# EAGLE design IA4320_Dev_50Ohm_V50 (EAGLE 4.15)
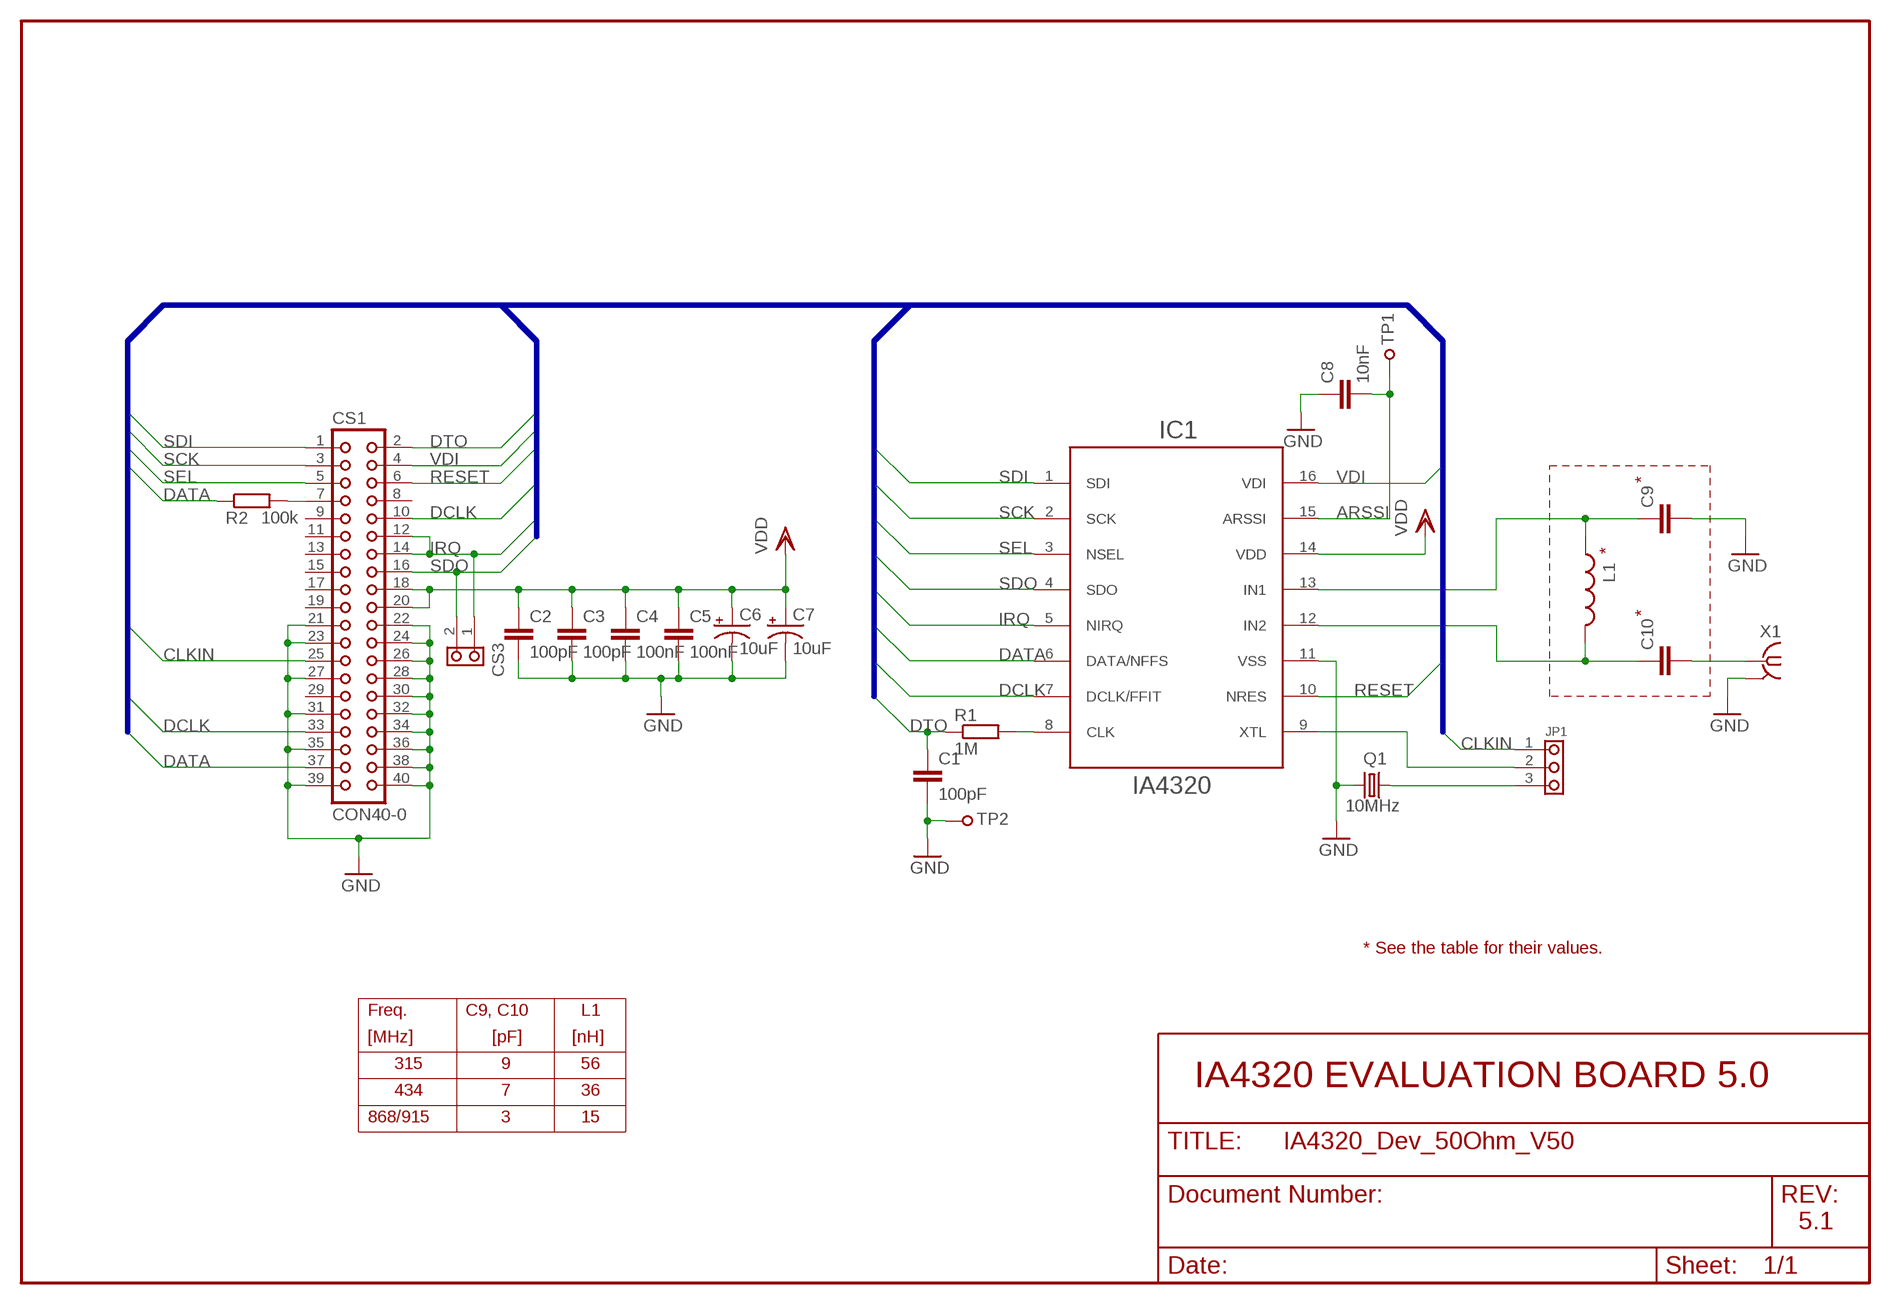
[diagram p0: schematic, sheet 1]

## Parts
C1  100pF  C-EUC0603  [C0603]
C2  100pF  C-EUC0603  [C0603]
C3  100pF  C-EUC0603  [C0603]
C4  100nF  C-EUC0603  [C0603]
C5  100nF  C-EUC0603  [C0603]
C6  10uF  CPOL-USA/3216-18R  [A/3216-18R]
C7  10uF  CPOL-USA/3216-18R  [A/3216-18R]
C8  10nF  C-EUC0603  [C0603]
C9  C-EUC0603  [C0603]
C10  C-EUC0603  [C0603]
CS1  CON40-0  [PANDUIT-057-040-0-INTEGRATION]
CS3  CRS-2  [CRS-2]
IC1  IA4320  RITATSSOP  [TSSOP-16]
JP1  JUMPER3  [PIN3]
L1  INDUCTCOILCRAFT-0805  [L2012]
Q1  10MHz  CRYTALSM49  [SM49]
R1  1M  R-EU_R0603  [R0603]
R2  100k  R-EU_R0603  [R0603]
TP1  TESTPOINT  TESTPOINT39MIL  [TESTPOINT1,0]
TP2  TESTPOINT39MIL  [TESTPOINT1,0]
X1  BU-SMA-H  [BU-SMA-H]

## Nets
ARSSI: C8.2 IC1.15(ARSSI) TP1.1
CLKIN: CS1.25 JP1.1
DATA: CS1.37 IC1.6(DATA/NFFS) R2.1
DCLK: CS1.10 CS1.33 IC1.7(DCLK/FFIT)
DTO: C1.1 CS1.2 R1.1
GND: C1.2 C2.2 C3.2 C4.2 C5.2 C6.- C7.- C8.1 C9.2 CS1.21 CS1.22 CS1.23 CS1.24 CS1.26 CS1.27 CS1.28 CS1.30 CS1.31 CS1.32 CS1.34 CS1.35 CS1.36 CS1.38 CS1.39 CS1.40 IC1.11(VSS) Q1.2 TP2.1 X1.2(GND)
IRQ: CS1.12 CS1.14 CS3.1(A) IC1.5(NIRQ)
N$1: CS1.7 R2.2
N$2: C9.1 IC1.13(IN1) L1.1
N$3: IC1.8(CLK) R1.2
N$4: IC1.9(XTL) JP1.2
N$5: C10.1 IC1.12(IN2) L1.2
N$6: JP1.3 Q1.1
N$8: C10.2 X1.1
RESET: CS1.6 IC1.10(NRES)
SCK: CS1.3 IC1.2(SCK)
SDI: CS1.1 IC1.1(SDI)
SDO: CS1.16 CS3.2(B) IC1.4(SDO)
SEL: CS1.5 IC1.3(NSEL)
VDD: C2.1 C3.1 C4.1 C5.1 C6.+ C7.+ CS1.18 CS1.20 IC1.14(VDD)
VDI: CS1.4 IC1.16(VDI)
Unconnected: CS1.8 CS1.9 CS1.11 CS1.13 CS1.15 CS1.17 CS1.19 CS1.29

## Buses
B$1

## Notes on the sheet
- *
- *
- *
- * See the table for their values.
- Freq. | C9, C10 | L1
- [MHz] | [pF] | [nH]
- 315 | 9 | 56
- IA4320 EVALUATION BOARD 5.0
- 434 | 7 | 36
- 868/915 | 3 | 15
- 5.1

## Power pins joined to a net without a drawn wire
GND: X1.3(GND) X1.4(GND) X1.5(GND)

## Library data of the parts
C1-C5 C8-C10 = rcl:C-EU: CAPACITOR, European symbol
C6 C7 = rcl:CPOL-US: POLARIZED CAPACITOR, American symbol
CS1 = lve:CON40
CS3 = lve:CRS-2: 2.54mm-es tuskesor krimpelheto csatlakozohoz
IC1 = lve:RITA: RITA
JP1 = lve:JUMPER3
L1 = lve:INDUCT
Q1 = crystal:CRYTAL: CRYSTAL
R1 R2 = rcl:R-EU_: RESISTOR, European symbol
TP1 TP2 = lve:TESTPOINT
X1 = con-coax:BU-SMA-H: FEMALE SMA CONNECTOR Radiall distributor RS 193-9325

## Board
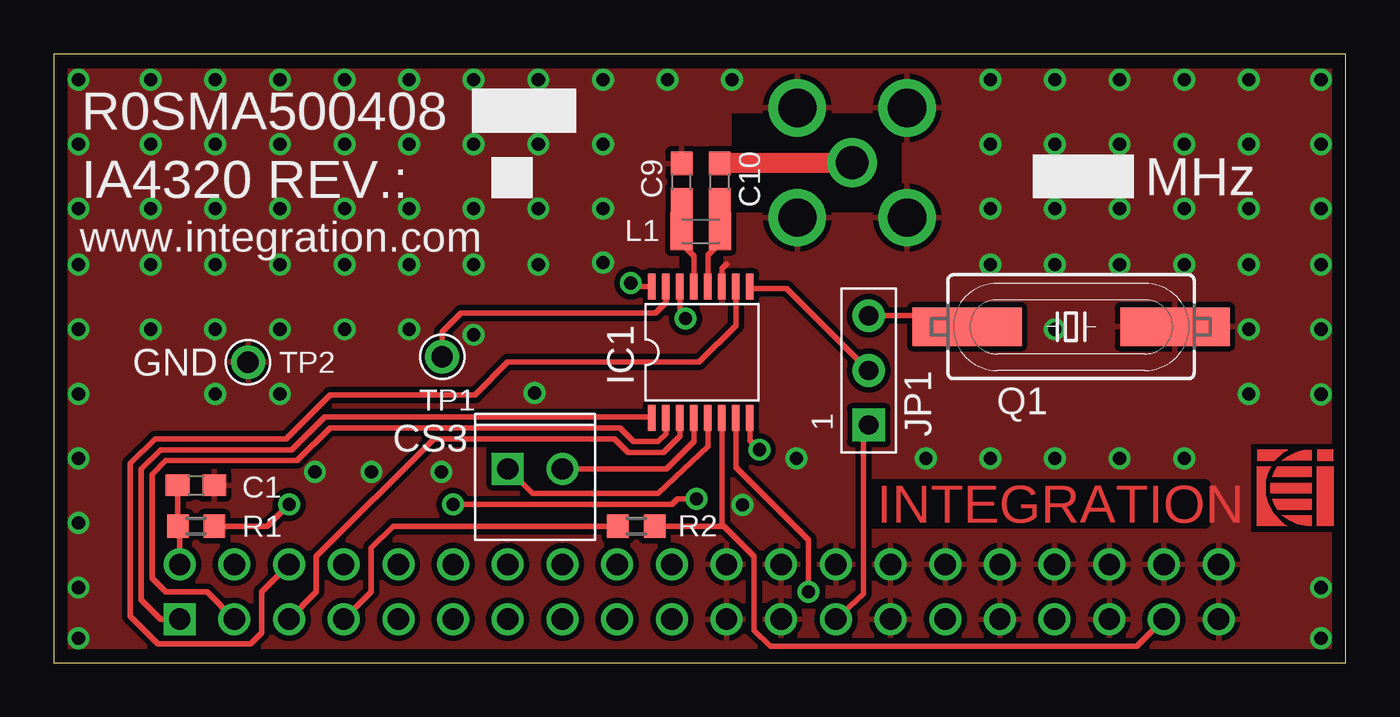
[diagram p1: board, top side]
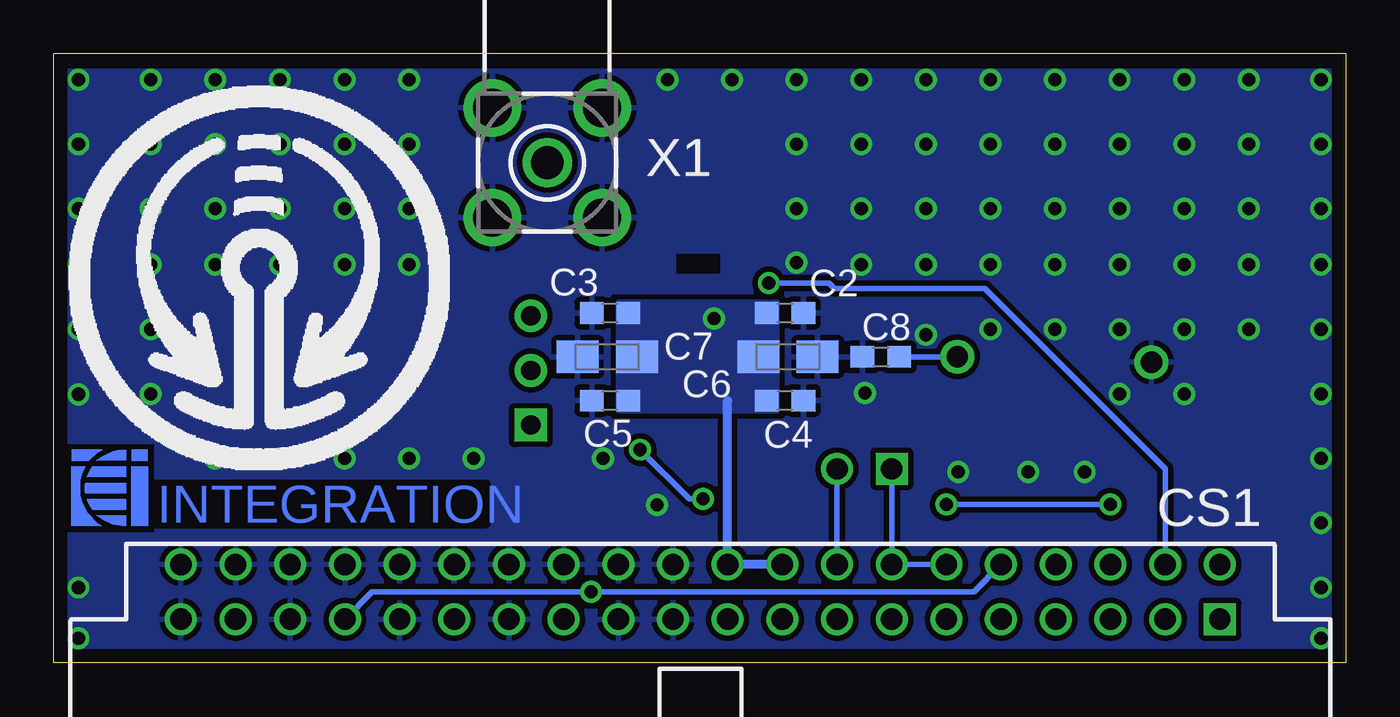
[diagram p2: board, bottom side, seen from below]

Size 60 x 28.3 mm. Coordinates in mm from the lower left corner, seen from the top.
Outline: 0,0 60,0 60,28.3 0,28.3 0,0
Copper layers (1*16): Top 0.035mm / dielectric 1.5mm / Bottom 0.035mm
Design rules "default_INTEGRATION": minimum track width 10mil, minimum drill 24mil, track to track 10mil, track to pad 10mil, pad to pad 10mil, via to via 10mil, smd to smd 10mil, copper to edge 25mil, drill to drill 8mil, minimum pad ring 8mil, minimum via ring 8mil, stop-mask expansion 4mil, vias tented up to drill 24mil, thermal gap 10mil
tRestrict: area 29.1,18.1 to 31.1,19; area 30.7,17.1 to 30.9,17.8; area 31.2,17.1 to 31.4,17.8; area 31.5,21 to 39.4,25.5; 4 lines
bRestrict: area 29.1,18.1 to 31.1,19; 5 lines

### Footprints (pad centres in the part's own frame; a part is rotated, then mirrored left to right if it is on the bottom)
C0603 = smd 1.1 x 1: 1 -0.85,0; 2 0.85,0
A/3216-18R = smd 1.95 x 1.5: + 1.375,0; - -1.375,0
PANDUIT-057-040-0-INTEGRATION = drill 0.991 square: 1 -24.13,-1.27 | drill 0.991 round: 2 -24.13,-3.81; 3 -21.59,-1.27; 4 -21.59,-3.81; 5 -19.05,-1.27; 6 -19.05,-3.81; 7 -16.51,-1.27; 8 -16.51,-3.81; 9 -13.97,-1.27; 10 -13.97,-3.81; 11 -11.43,-1.27; 12 -11.43,-3.81; 13 -8.89,-1.27; 14 -8.89,-3.81; 15 -6.35,-1.27; 16 -6.35,-3.81; 17 -3.81,-1.27; 18 -3.81,-3.81; 19 -1.27,-1.27; 20 -1.27,-3.81; 21 1.27,-1.27; 22 1.27,-3.81; 23 3.81,-1.27; 24 3.81,-3.81; 25 6.35,-1.27; 26 6.35,-3.81; 27 8.89,-1.27; 28 8.89,-3.81; 29 11.43,-1.27; 30 11.43,-3.81; 31 13.97,-1.27; 32 13.97,-3.81; 33 16.51,-1.27; 34 16.51,-3.81; 35 19.05,-1.27; 36 19.05,-3.81; 37 21.59,-1.27; 38 21.59,-3.81; 39 24.13,-1.27; 40 24.13,-3.81
CRS-2 = drill 0.991 square: 1 -1.27,0 | drill 0.991 round: 2 1.27,0
TSSOP-16 = smd 1.2 x 0.35: 1 -3.107,2.223; 2 -3.107,1.573; 3 -3.107,0.922; 4 -3.107,0.273; 5 -3.107,-0.378; 6 -3.107,-1.028; 7 -3.107,-1.677; 8 -3.107,-2.328; 9 2.993,-2.328; 10 2.993,-1.677; 11 2.993,-1.028; 12 2.993,-0.378; 13 2.993,0.273; 14 2.993,0.922; 15 2.993,1.573; 16 2.993,2.223
PIN3 = drill 0.889 pad 1.524 square: 1 -2.54,0 | drill 0.889 pad 1.524 round: 2 0,0; 3 2.54,0
L2012 = smd 1.016 x 1.778: 1 -0.889,0; 2 0.889,0
SM49 = smd 5.08 x 1.778: 1 -4.826,0; 2 4.826,0
R0603 = smd 1 x 1.1: 1 -0.85,0; 2 0.85,0
TESTPOINT1,0 = drill 0.991 pad 1.575 round: 1 0,0
BU-SMA-H = drill 1.524 round: 1 0,0 | drill 1.778 round: 2 -2.55,2.55; 3 2.55,2.55; 4 2.55,-2.55; 5 -2.55,-2.55

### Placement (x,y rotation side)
C1  6.6,8.26 0 top
C2  26.04,16.26 0 bottom
C3  34.16,16.26 180 bottom
C4  26.04,12.19 0 bottom
C5  34.16,12.19 180 bottom
C6  25.91,14.22 180 bottom
C7  34.29,14.22 0 bottom
C8  21.59,14.22 0 bottom
C9  29.16,22.35 90 top
C10  30.94,22.35 90 top
CS1  29.97,0.76 180 bottom
CS3  22.35,9.02 0 top
IC1  30,14.49 90 top
JP1  37.85,13.59 90 top
L1  30.05,20.07 0 top
Q1  47.24,15.62 0 top
R1  6.6,6.35 0 top
R2  27.05,6.35 180 top
TP1  18.03,14.22 0 top
TP2  9.02,13.97 0 top
U$1  [RECEIVE-ICON]  50.44,18.29 0 bottom
U$2  [LOGO-SMALL]  57.66,8.13 0 top
U$3  [LOGO-SMALL]  57.4,8.13 0 bottom
X1  37.08,23.24 90 bottom

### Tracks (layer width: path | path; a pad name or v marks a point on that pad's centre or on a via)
ARSSI
  Top 0.254: IC1.15 28.43,16.74 27.94,16.26 18.92,16.26 18.03,15.37 TP1.1
  Bottom 0.254: TP1.1 C8.2
CLKIN
  Top 0.254: CS1.25 37.59,3.2 37.59,10.79 | 37.59,10.79 37.59,10.8 | 37.59,10.79 JP1.1
DATA
  Top 0.254: R2.1 27.9,6.4 | R2.1 31.03,6.35 | R2.1 27.9,6.3 | 31.03,6.35 IC1.6 | 31.03,6.35 31.11,6.35 32.51,4.95 32.51,1.52 33.27,0.76 50.29,0.76 CS1.37
DCLK  (via drill 0.61 pad 1.02)
  Top 0.254: v35.05,3.3 35.05,5.71 31.68,9.09 IC1.7
  Bottom 0.254: CS1.10 17.27,3.3 v35.05,3.3 45.21,3.3 CS1.33
DTO
  Top 0.254: C1.1 5.75,6.39 5.71,6.35 | 5.71,6.35 R1.1 | CS1.2 5.84,6.22 5.71,6.35
GND  (via drill 0.61 pad 1.02)
  Top 0.254: IC1.11 31.02,18.32 31.24,18.54
  other vias: 1.15,27.1 25.5,27.1 22.5,27.1 19.5,27.1 16.5,27.1 13.5,27.1 10.5,27.1 7.5,27.1 4.5,27.1 43.5,27.1 46.5,27.1 49.5,27.1 52.5,27.1 55.5,27.1 58.85,27.1 58.85,15.5 58.85,12.48 58.85,3.5 58.85,1.15 1.15,15.5 1.15,12.5 1.15,9.5 1.15,6.5 1.15,3.5 1.15,1.15 14.75,8.87 12.12,8.87 4.5,15.5 7.5,15.5 10.5,15.5 13.5,15.5 16.5,15.5 19.5,15.25 55.5,15.5 46.5,15.5 18,8.87 22.33,12.54 52.5,9.5 46.5,9.5 40.5,9.5 7.5,12.5 10.5,12.5 34.5,9.5 31.98,7.35 4.5,18.5 7.5,18.5 10.5,18.5 13.5,18.5 16.5,18.5 19.5,18.5 22.5,18.5 25.5,18.6 1.15,18.5 4.5,21.1 4.5,24.1 1.15,24.1 7.5,24.1 10.5,24.1 13.5,24.1 16.5,24.1 19.5,24.1 22.5,24.1 25.5,24.1 28.5,27.1 31.5,27.1 25.5,21.1 22.5,21.1 19.5,21.1 16.5,21.1 13.5,21.1 10.5,21.1 7.5,21.1 1.15,21.1 43.5,24.1 46.5,24.1 49.5,24.1 52.5,24.1 55.5,24.1 58.85,24.1 43.5,21.1 46.5,21.1 49.5,21.1 52.5,21.1 55.5,21.1 58.85,21.1 43.5,18.5 46.5,18.5 49.5,18.5 52.5,18.5 55.5,18.5 58.85,18.5 49.5,9.5 43.5,9.5 55.5,12.5
  pour Bottom (rank 2): 0,0 0,27.5 60,27.5 60,0
  pour Top (rank 2): 0,0 0,27.5 60,27.5 60,0
IRQ
  Top 0.254: IC1.5 30.38,10.06 28.07,7.87 22.23,7.87 CS3.1
  Bottom 0.254: CS3.1 CS1.14 CS1.12
N$1
  Top 0.254: R2.2 15.75,6.35 14.73,5.33 14.73,3.3 CS1.7
N$2
  Top 0.254: IC1.13 29.73,18.91 29.16,19.48 L1.1 C9.1
N$3  (via drill 0.61 pad 1.02)
  Top 0.254: R1.2 9.91,6.35 v10.92,7.37 | v18.54,7.37 28.7,7.37 28.96,7.62 v29.84,7.62 | IC1.8 32.33,10.35 v32.77,9.91
  Bottom 0.254: v10.92,7.37 v18.54,7.37 | v29.84,7.62 30.48,7.62 v32.77,9.91
N$4
  Top 0.254: IC1.9 32.38,17.43 32.38,17.4 34.04,17.4 JP1.2
N$5
  Top 0.254: IC1.12 30.38,18.95 30.94,19.51 L1.2 C10.1
N$6
  Top 0.254: 42.31,15.57 Q1.1 | 42.31,15.57 42.29,15.56 | 42.31,15.57 42.31,15.6 41.78,16.13 JP1.3
N$8
  Top 0.92: C10.2 30.99,23.24 X1.1
RESET
  Top 0.254: IC1.10 31.68,15.68 29.97,13.97 21.08,13.97 19.56,12.45 12.83,12.45 10.79,10.41 4.7,10.41 3.56,9.27 3.56,2.16 4.83,0.89 9.14,0.89 9.65,1.4 9.65,3.3 CS1.6
SCK
  Top 0.254: IC1.2 28.43,10.65 28.07,10.29 26.92,10.29 26.29,10.92 12.83,10.92 11.3,9.4 5.21,9.4 4.57,8.76 4.57,3.94 5.21,3.3 7.11,3.3 CS1.3
SDI
  Top 0.254: CS1.1 4.95,2.03 4.06,2.92 4.06,9.02 4.95,9.91 11.05,9.91 12.57,11.43 27.73,11.43 IC1.1
SDO
  Top 0.254: IC1.4 29.73,10.3 28.45,9.02 CS3.2
  Bottom 0.254: CS1.16 CS3.2
SEL
  Top 0.254: IC1.3 29.08,10.54 28.32,9.78 26.67,9.78 26.04,10.41 17.65,10.41 12.19,4.95 12.19,3.3 CS1.5
VDD  (via drill 0.61 pad 1.02)
  Top 0.254: IC1.14 29.08,16.26 v29.34,16
  Bottom 0.406: CS1.18 CS1.20 28.7,12.19
  pour Bottom (no thermals): 26.42,16.76 33.78,16.76 33.78,11.71 26.42,11.71
VDI  (via drill 0.61 pad 1.02)
  Top 0.254: IC1.16 26.97,17.48 v26.8,17.65
  Bottom 0.254: v26.8,17.65 24,17.65 23.75,17.4 16.76,17.4 8.38,9.02 CS1.4

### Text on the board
Top: INTEGRATION
Bottom: INTEGRATION
tPlace: R0SMA500408 | IA4320 REV.: | MHz | www.integration.com | GND | 1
